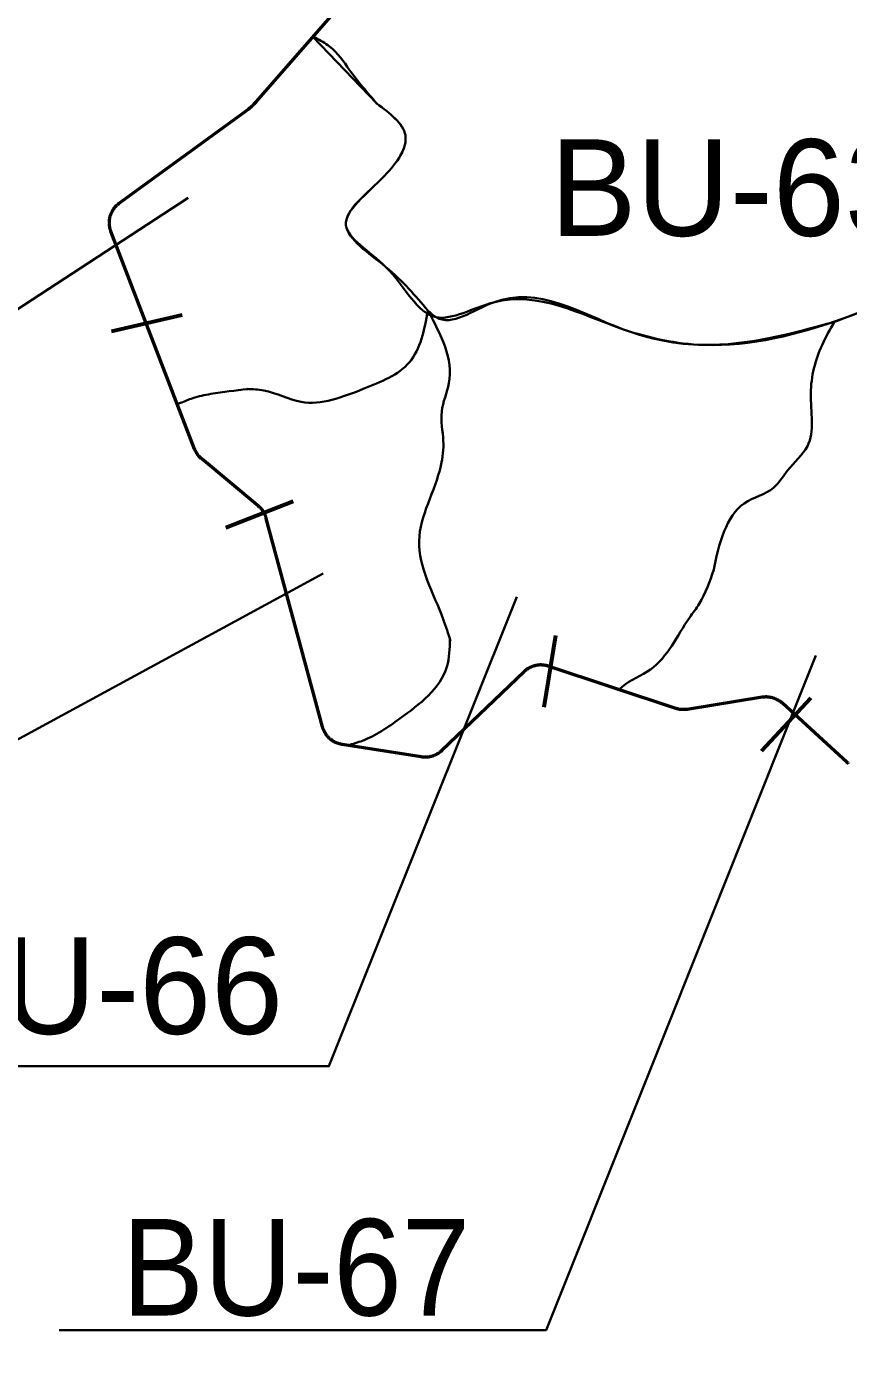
# Model space of a CAD drawing. Extents: x 553962 to 842807, y 8883888 to 9032388.
# Drawn here: x 651378 to 654778, y 8952723 to 8958207 of the extents above; entities that cross this region are included whole.
import ezdxf

# ---------------------------------------------------------------- set-up
doc = ezdxf.new("R2010")
doc.units = 0
doc.header["$LTSCALE"] = 150
for name, color, linetype, lineweight in [('20', 7, 'Continuous', 35), ('40', 7, 'Continuous', 60), ('60', 7, 'Continuous', 53), ('9', 7, 'Continuous', 90)]:
    doc.layers.add(name, color=color, linetype=linetype, lineweight=lineweight)

msp = doc.modelspace()

# ---------------------------------------------------------------- linework, layer by layer
at = {"layer": '20'}
for p, q in [((652563.7, 8958165), (653032.2, 8958701.7)), ((652563.2, 8958164.5), (652826.9, 8957888.7)), ((654720.4, 8956985.1), (654717.3, 8956984)), ((652293, 8956706.9), (652289, 8956707.3)), ((653830.5, 8955462.4), (653829, 8955462.9))]:
    msp.add_line(p, q, dxfattribs=at)
for points in [[(652002.6, 8956643.4), (651727.4, 8957359.4), (651726.4, 8957362), (651725.5, 8957364.7), (651724.7, 8957367.4), (651723.9, 8957370.2), (651723.2, 8957372.9), (651722.7, 8957375.7), (651722.1, 8957378.4), (651721.7, 8957381.2), (651721.3, 8957384), (651721.1, 8957386.9), (651720.9, 8957389.7), (651720.8, 8957392.5), (651720.7, 8957395.3), (651720.8, 8957398.2), (651720.9, 8957401), (651721.1, 8957403.8), (651721.4, 8957406.6), (651721.7, 8957409.4), (651722.2, 8957412.2), (651722.7, 8957415), (651723.3, 8957417.8), (651724, 8957420.5), (651724.7, 8957423.2), (651725.5, 8957425.9), (651726.4, 8957428.6), (651727.4, 8957431.3), (651728.5, 8957433.9), (651729.6, 8957436.5), (651730.8, 8957439.1), (651732.1, 8957441.6), (651733.4, 8957444.1), (651734.8, 8957446.5), (651736.3, 8957448.9), (651737.9, 8957451.3), (651739.5, 8957453.6), (651741.2, 8957455.9), (651742.9, 8957458.1), (651744.7, 8957460.3), (651746.6, 8957462.4), (651748.5, 8957464.5), (651750.5, 8957466.5), (651752.6, 8957468.4), (651754.7, 8957470.3), (651756.8, 8957472.2), (651759, 8957474), (651761.3, 8957475.7), (651761.8, 8957476), (652295.9, 8957865.8), (652299.1, 8957868.2), (652302.3, 8957870.6), (652305.4, 8957873.1), (652308.4, 8957875.7), (652311.5, 8957878.3), (652314.4, 8957881.1), (652317.3, 8957883.8), (652320.1, 8957886.6), (652322.9, 8957889.5), (652325.7, 8957892.4), (652328.3, 8957895.4), (652328.7, 8957895.8), (652563.2, 8958164.5)], [(652089.1, 8956431.6), (652087.4, 8956433.8), (652085.7, 8956436.1), (652084.1, 8956438.5), (652082.6, 8956440.8), (652081.1, 8956443.2), (652079.7, 8956445.7), (652078.3, 8956448.2), (652077, 8956450.7), (652075.8, 8956453.2), (652074.7, 8956455.8), (652073.7, 8956458.5), (652073.6, 8956458.6), (652003.1, 8956642.1)], [(652710.8, 8955231.7), (652683.3, 8955236.1), (652680.5, 8955236.5), (652677.7, 8955237.1), (652675, 8955237.7), (652672.2, 8955238.5), (652669.5, 8955239.2), (652666.8, 8955240.1), (652664.1, 8955241.1), (652661.5, 8955242.1), (652658.9, 8955243.2), (652656.3, 8955244.4), (652653.8, 8955245.6), (652651.3, 8955246.9), (652648.8, 8955248.3), (652646.4, 8955249.8), (652644, 8955251.3), (652641.7, 8955252.9), (652639.4, 8955254.5), (652637.1, 8955256.2), (652634.9, 8955258), (652632.8, 8955259.8), (652630.7, 8955261.8), (652628.6, 8955263.7), (652626.7, 8955265.7), (652624.7, 8955267.8), (652622.9, 8955269.9), (652621.1, 8955272.1), (652619.3, 8955274.3), (652617.6, 8955276.6), (652616, 8955278.9), (652614.5, 8955281.3), (652613, 8955283.7), (652611.6, 8955286.2), (652610.2, 8955288.7), (652609, 8955291.2), (652607.8, 8955293.7), (652606.7, 8955296.3), (652605.6, 8955299), (652604.6, 8955301.6), (652603.7, 8955304.3), (652602.9, 8955307), (652602.4, 8955308.8), (652370.1, 8956171.6), (652369.3, 8956174.3), (652368.5, 8956177.1), (652367.6, 8956179.7), (652366.6, 8956182.4), (652365.5, 8956185), (652364.3, 8956187.6), (652363.1, 8956190.1), (652361.8, 8956192.6), (652360.5, 8956195.1), (652359, 8956197.6), (652357.5, 8956199.9), (652356, 8956202.3), (652354.3, 8956204.6), (652352.6, 8956206.9), (652350.9, 8956209.1), (652349, 8956211.2), (652347.2, 8956213.3), (652345.2, 8956215.4), (652343.2, 8956217.4), (652341.1, 8956219.3), (652339, 8956221.2), (652337.5, 8956222.5), (652103, 8956417.5), (652100.9, 8956419.4), (652098.8, 8956421.3), (652096.7, 8956423.2), (652094.7, 8956425.3), (652092.8, 8956427.3), (652091, 8956429.5), (652089.1, 8956431.6)], [(653082.6, 8955200), (653084.9, 8955201.6), (653087.2, 8955203.2), (653089.4, 8955205), (653091.6, 8955206.8), (653093.7, 8955208.7), (653095.8, 8955210.6), (653436.2, 8955537), (653436.9, 8955537.7), (653439, 8955539.6), (653441.1, 8955541.4), (653443.3, 8955543.2), (653445.5, 8955545), (653447.8, 8955546.6), (653450.2, 8955548.2), (653452.5, 8955549.7), (653455, 8955551.2), (653457.4, 8955552.6), (653459.9, 8955553.9), (653462.5, 8955555.2), (653465, 8955556.3), (653467.6, 8955557.4), (653470.3, 8955558.5), (653472.9, 8955559.4), (653475.6, 8955560.3), (653478.3, 8955561.1), (653481.1, 8955561.8), (653483.8, 8955562.5), (653486.6, 8955563.1), (653489.4, 8955563.5), (653492.2, 8955564), (653495, 8955564.3), (653497.8, 8955564.6), (653500.6, 8955564.7), (653503.5, 8955564.8), (653506.3, 8955564.8), (653509.1, 8955564.8), (653511.9, 8955564.6), (653514.8, 8955564.4), (653517.6, 8955564.1), (653520.4, 8955563.7), (653523.2, 8955563.2), (653525.9, 8955562.7), (653528.7, 8955562.1), (653531.4, 8955561.4), (653534.2, 8955560.6), (653536.8, 8955559.8), (653829.5, 8955462.7)], [(654774.8, 8955159.6), (654772.6, 8955161.5), (654771.6, 8955162.4), (654505.1, 8955406.1), (654503, 8955408), (654500.8, 8955409.8), (654498.6, 8955411.6), (654496.4, 8955413.3), (654494.1, 8955414.9), (654491.7, 8955416.5), (654489.3, 8955418), (654486.9, 8955419.4), (654484.4, 8955420.7), (654481.8, 8955422), (654479.3, 8955423.2), (654476.7, 8955424.4), (654474.1, 8955425.4), (654471.5, 8955426.4), (654468.8, 8955427.3), (654466.1, 8955428.2), (654463.3, 8955429), (654460.6, 8955429.7), (654457.8, 8955430.3), (654455.1, 8955430.8), (654452.3, 8955431.2), (654449.5, 8955431.6), (654446.7, 8955431.9), (654443.8, 8955432.1), (654441, 8955432.3), (654438.2, 8955432.3), (654435.4, 8955432.3), (654432.5, 8955432.2), (654429.7, 8955432), (654426.9, 8955431.7), (654424.1, 8955431.4), (654421.8, 8955431.1), (654111.4, 8955381.1), (654108.6, 8955380.7), (654105.8, 8955380.4), (654103, 8955380.2), (654100.1, 8955380), (654097.3, 8955379.9), (654094.5, 8955379.9), (654091.7, 8955379.9), (654088.8, 8955380.1), (654086, 8955380.3), (654083.2, 8955380.6), (654080.4, 8955381), (654077.6, 8955381.5), (654074.8, 8955382), (654072.1, 8955382.7), (654069.3, 8955383.3), (654066.6, 8955384.1), (654064, 8955385), (653830.5, 8955462.4)], [(652712.1, 8955231.5), (653010.9, 8955184), (653012.6, 8955183.8), (653015.4, 8955183.4), (653018.2, 8955183.1), (653021, 8955182.9), (653023.8, 8955182.8), (653026.7, 8955182.8), (653029.5, 8955182.8), (653032.3, 8955183), (653035.1, 8955183.2), (653037.9, 8955183.4), (653040.7, 8955183.8), (653043.5, 8955184.2), (653046.3, 8955184.8), (653049.1, 8955185.3), (653051.8, 8955186), (653054.6, 8955186.8), (653057.3, 8955187.6), (653059.9, 8955188.5), (653062.6, 8955189.5), (653065.2, 8955190.6), (653067.8, 8955191.7), (653070.4, 8955192.9), (653072.9, 8955194.2), (653075.4, 8955195.5), (653077.8, 8955196.9), (653080.2, 8955198.4), (653082.6, 8955200)]]:
    msp.add_lwpolyline(points, dxfattribs=at)
for points in [[(657836.1, 8962063), (657516.9, 8961702.6), (657287.8, 8961510.1), (657005.4, 8961440.5), (656903.1, 8961280.8), (656489.7, 8960883.6), (656367, 8960554), (656244.2, 8960275.5), (656461.1, 8960083), (656125.5, 8959583.5), (656002.7, 8959268.1), (655892.2, 8958970.8), (655875.9, 8958766.1), (655834.9, 8958479.4), (655843.5, 8958403.3), (655810.8, 8958169.9), (655724.8, 8957948.7), (655561.2, 8957592.5), (655350, 8957384.8), (655198.6, 8957233.3), (654760.7, 8956999.9), (654179.6, 8956889.4), (653844, 8956954.9), (653309.5, 8957065.4), (653072.2, 8957004), (652863.4, 8957212.9), (652699.7, 8957384.8), (652859.3, 8957589.6), (652945.3, 8957757.5), (652826.9, 8957888.7)], [(652827.9, 8957887.6), (652714.5, 8958027.3), (652632.2, 8958124.7), (652573, 8958160.8), (652564.3, 8958165.8)], [(652827.9, 8957887.6), (652714.5, 8958027.3), (652632.2, 8958124.7), (652573, 8958160.8), (652564.3, 8958165.8)], [(653037.9, 8957032.2), (652863.4, 8957212.9), (652699.7, 8957384.8), (652859.3, 8957589.6), (652945.3, 8957757.5), (652826.9, 8957888.7)], [(652826.9, 8957888.7), (652945.3, 8957757.5), (652859.3, 8957589.6), (652699.7, 8957384.8), (652863.4, 8957212.9), (653037.9, 8957032.2)], [(655331.3, 8957366.2), (655198.6, 8957233.3), (654760.7, 8956999.9), (654718.7, 8956984.5)], [(654718.7, 8956984.5), (654760.7, 8956999.9), (655198.6, 8957233.3), (655331.3, 8957366.2)], [(654717.3, 8956984), (654179.6, 8956889.4), (653844, 8956954.9), (653309.5, 8957065.4), (653072.2, 8957004), (653039.2, 8957031.1)], [(654717.3, 8956984), (654179.6, 8956889.4), (653844, 8956954.9), (653309.5, 8957065.4), (653072.2, 8957004), (653039.2, 8957031.1)], [(653039.1, 8957031.2), (652961.9, 8956817.7), (652771.4, 8956707.3), (652514, 8956653.8), (652360.2, 8956700.6), (652289, 8956707.3)], [(652289, 8956707.3), (652360.2, 8956700.6), (652514, 8956653.8), (652771.4, 8956707.3), (652961.9, 8956817.7), (653039.1, 8957031.2)], [(652289, 8956707.3), (652360.2, 8956700.6), (652514, 8956653.8), (652771.4, 8956707.3), (652961.9, 8956817.7), (653039.1, 8957031.2)], [(653038.9, 8957031.4), (653125.7, 8956730.7), (653095.6, 8956613.6), (653102.3, 8956493.2), (653092.3, 8956389.5), (653002, 8956078.4), (653102.3, 8955753.9), (653132.4, 8955663.6)], [(653038.9, 8957031.4), (653125.7, 8956730.7), (653095.6, 8956613.6), (653102.3, 8956493.2), (653092.3, 8956389.5), (653002, 8956078.4), (653102.3, 8955753.9), (653132.4, 8955663.6)], [(653038.9, 8957031.4), (653125.7, 8956730.7), (653095.6, 8956613.6), (653102.3, 8956493.2), (653092.3, 8956389.5), (653002, 8956078.4), (653102.3, 8955753.9), (653132.4, 8955663.6)], [(654219.7, 8955952.5), (654264.8, 8956119.1), (654347.1, 8956233.7), (654468.8, 8956298.1), (654526, 8956369.7), (654608.3, 8956470), (654622.6, 8956688.4), (654669.2, 8956888.9), (654720.4, 8956985.1)], [(654219.7, 8955952.5), (654264.8, 8956119.1), (654347.1, 8956233.7), (654468.8, 8956298.1), (654526, 8956369.7), (654608.3, 8956470), (654622.6, 8956688.4), (654669.2, 8956888.9), (654720.4, 8956985.1)], [(654720.4, 8956985.1), (654669.2, 8956888.9), (654622.6, 8956688.4), (654608.3, 8956470), (654526, 8956369.7), (654468.8, 8956298.1), (654347.1, 8956233.7), (654264.8, 8956119.1), (654219.7, 8955952.5)], [(652293, 8956706.9), (652140.8, 8956686.4), (652065.6, 8956669.2), (652014.8, 8956649.2), (652002.2, 8956644.5)], [(652002.2, 8956644.5), (652014.8, 8956649.2), (652065.6, 8956669.2), (652140.8, 8956686.4), (652293, 8956706.9)], [(652293, 8956706.9), (652140.8, 8956686.4), (652065.6, 8956669.2), (652014.8, 8956649.2), (652002.2, 8956644.5)], [(653829, 8955462.9), (653842.3, 8955474.7), (653958.9, 8955546.1), (654120.8, 8955760.3), (654160.8, 8955817.8), (654221.6, 8955959.4)], [(653829, 8955462.9), (653842.3, 8955474.7), (653958.9, 8955546.1), (654120.8, 8955760.3), (654160.8, 8955817.8), (654221.6, 8955959.4)], [(654221.6, 8955959.4), (654160.8, 8955817.8), (654120.8, 8955760.3), (653958.9, 8955546.1), (653842.3, 8955474.7), (653829, 8955462.9)], [(653129.6, 8955672.1), (653117.4, 8955557.7), (652922.6, 8955342.6), (652767.9, 8955251.3), (652707.6, 8955232.2)], [(653129.6, 8955672.1), (653117.4, 8955557.7), (652922.6, 8955342.6), (652767.9, 8955251.3), (652707.6, 8955232.2)], [(653129.6, 8955672.1), (653117.4, 8955557.7), (652922.6, 8955342.6), (652767.9, 8955251.3), (652707.6, 8955232.2)]]:
    msp.add_spline(points, degree=3, dxfattribs=at)
at = {"layer": '40'}
for p, q in [((651730.2, 8956946.1), (652022.6, 8957013.3)), ((652202.2, 8956133.9), (652481.5, 8956243.4)), ((653519.1, 8955390.6), (653567.9, 8955686.7)), ((654419, 8955209), (654623.3, 8955428.7))]:
    msp.add_line(p, q, dxfattribs=at)
at = {"layer": '40', "lineweight": 35}
for points in [[(652046.7, 8957498.3), (650857.4, 8956721.2), (649037.1, 8956721.2)], [(652604.9, 8955944), (651221.5, 8955191.1), (649182.7, 8955191.1)], [(653405.9, 8955846.9), (652629.2, 8953903.9), (650711.8, 8953903.9)], [(654643.7, 8955604), (653527.2, 8952811), (651512.7, 8952811)]]:
    msp.add_lwpolyline(points, dxfattribs=at)
at = {"layer": '60'}
for points in [[(652089.1, 8956431.6), (652087.4, 8956433.8), (652085.7, 8956436.1), (652084.1, 8956438.5), (652082.6, 8956440.8), (652081.1, 8956443.2), (652079.7, 8956445.7), (652078.3, 8956448.2), (652077, 8956450.7), (652075.8, 8956453.2), (652074.7, 8956455.8), (652073.7, 8956458.5), (652073.6, 8956458.6), (651727.4, 8957359.4), (651726.4, 8957362), (651725.5, 8957364.7), (651724.7, 8957367.4), (651723.9, 8957370.2), (651723.2, 8957372.9), (651722.7, 8957375.7), (651722.1, 8957378.4), (651721.7, 8957381.2), (651721.3, 8957384), (651721.1, 8957386.9), (651720.9, 8957389.7), (651720.8, 8957392.5), (651720.7, 8957395.3), (651720.8, 8957398.2), (651720.9, 8957401), (651721.1, 8957403.8), (651721.4, 8957406.6), (651721.7, 8957409.4), (651722.2, 8957412.2), (651722.7, 8957415), (651723.3, 8957417.8), (651724, 8957420.5), (651724.7, 8957423.2), (651725.5, 8957425.9), (651726.4, 8957428.6), (651727.4, 8957431.3), (651728.5, 8957433.9), (651729.6, 8957436.5), (651730.8, 8957439.1), (651732.1, 8957441.6), (651733.4, 8957444.1), (651734.8, 8957446.5), (651736.3, 8957448.9), (651737.9, 8957451.3), (651739.5, 8957453.6), (651741.2, 8957455.9), (651742.9, 8957458.1), (651744.7, 8957460.3), (651746.6, 8957462.4), (651748.5, 8957464.5), (651750.5, 8957466.5), (651752.6, 8957468.4), (651754.7, 8957470.3), (651756.8, 8957472.2), (651759, 8957474), (651761.3, 8957475.7), (651761.8, 8957476), (652295.9, 8957865.8), (652299.1, 8957868.2), (652302.3, 8957870.6), (652305.4, 8957873.1), (652308.4, 8957875.7), (652311.5, 8957878.3), (652314.4, 8957881.1), (652317.3, 8957883.8), (652320.1, 8957886.6), (652322.9, 8957889.5), (652325.7, 8957892.4), (652328.3, 8957895.4), (652328.7, 8957895.8), (653033.4, 8958703.2)], [(653082.6, 8955200), (653080.2, 8955198.4), (653077.8, 8955196.9), (653075.4, 8955195.5), (653072.9, 8955194.2), (653070.4, 8955192.9), (653067.8, 8955191.7), (653065.2, 8955190.6), (653062.6, 8955189.5), (653059.9, 8955188.5), (653057.3, 8955187.6), (653054.6, 8955186.8), (653051.8, 8955186), (653049.1, 8955185.3), (653046.3, 8955184.8), (653043.5, 8955184.2), (653040.7, 8955183.8), (653037.9, 8955183.4), (653035.1, 8955183.2), (653032.3, 8955183), (653029.5, 8955182.8), (653026.7, 8955182.8), (653023.8, 8955182.8), (653021, 8955182.9), (653018.2, 8955183.1), (653015.4, 8955183.4), (653012.6, 8955183.8), (653010.9, 8955184), (652683.3, 8955236.1), (652680.5, 8955236.5), (652677.7, 8955237.1), (652675, 8955237.7), (652672.2, 8955238.5), (652669.5, 8955239.2), (652666.8, 8955240.1), (652664.1, 8955241.1), (652661.5, 8955242.1), (652658.9, 8955243.2), (652656.3, 8955244.4), (652653.8, 8955245.6), (652651.3, 8955246.9), (652648.8, 8955248.3), (652646.4, 8955249.8), (652644, 8955251.3), (652641.7, 8955252.9), (652639.4, 8955254.5), (652637.1, 8955256.2), (652634.9, 8955258), (652632.8, 8955259.8), (652630.7, 8955261.8), (652628.6, 8955263.7), (652626.7, 8955265.7), (652624.7, 8955267.8), (652622.9, 8955269.9), (652621.1, 8955272.1), (652619.3, 8955274.3), (652617.6, 8955276.6), (652616, 8955278.9), (652614.5, 8955281.3), (652613, 8955283.7), (652611.6, 8955286.2), (652610.2, 8955288.7), (652609, 8955291.2), (652607.8, 8955293.7), (652606.7, 8955296.3), (652605.6, 8955299), (652604.6, 8955301.6), (652603.7, 8955304.3), (652602.9, 8955307), (652602.4, 8955308.8), (652370.1, 8956171.6), (652369.3, 8956174.3), (652368.5, 8956177.1), (652367.6, 8956179.7), (652366.6, 8956182.4), (652365.5, 8956185), (652364.3, 8956187.6), (652363.1, 8956190.1), (652361.8, 8956192.6), (652360.5, 8956195.1), (652359, 8956197.6), (652357.5, 8956199.9), (652356, 8956202.3), (652354.3, 8956204.6), (652352.6, 8956206.9), (652350.9, 8956209.1), (652349, 8956211.2), (652347.2, 8956213.3), (652345.2, 8956215.4), (652343.2, 8956217.4), (652341.1, 8956219.3), (652339, 8956221.2), (652337.5, 8956222.5), (652103, 8956417.5), (652100.9, 8956419.4), (652098.8, 8956421.3), (652096.7, 8956423.2), (652094.7, 8956425.3), (652092.8, 8956427.3), (652091, 8956429.5), (652089.1, 8956431.6)], [(654774.8, 8955159.6), (654772.6, 8955161.5), (654771.6, 8955162.4), (654505.1, 8955406.1), (654503, 8955408), (654500.8, 8955409.8), (654498.6, 8955411.6), (654496.4, 8955413.3), (654494.1, 8955414.9), (654491.7, 8955416.5), (654489.3, 8955418), (654486.9, 8955419.4), (654484.4, 8955420.7), (654481.8, 8955422), (654479.3, 8955423.2), (654476.7, 8955424.4), (654474.1, 8955425.4), (654471.5, 8955426.4), (654468.8, 8955427.3), (654466.1, 8955428.2), (654463.3, 8955429), (654460.6, 8955429.7), (654457.8, 8955430.3), (654455.1, 8955430.8), (654452.3, 8955431.2), (654449.5, 8955431.6), (654446.7, 8955431.9), (654443.8, 8955432.1), (654441, 8955432.3), (654438.2, 8955432.3), (654435.4, 8955432.3), (654432.5, 8955432.2), (654429.7, 8955432), (654426.9, 8955431.7), (654424.1, 8955431.4), (654421.8, 8955431.1), (654111.4, 8955381.1), (654108.6, 8955380.7), (654105.8, 8955380.4), (654103, 8955380.2), (654100.1, 8955380), (654097.3, 8955379.9), (654094.5, 8955379.9), (654091.7, 8955379.9), (654088.8, 8955380.1), (654086, 8955380.3), (654083.2, 8955380.6), (654080.4, 8955381), (654077.6, 8955381.5), (654074.8, 8955382), (654072.1, 8955382.7), (654069.3, 8955383.3), (654066.6, 8955384.1), (654064, 8955385), (653536.8, 8955559.8), (653534.2, 8955560.6), (653531.4, 8955561.4), (653528.7, 8955562.1), (653525.9, 8955562.7), (653523.2, 8955563.2), (653520.4, 8955563.7), (653517.6, 8955564.1), (653514.8, 8955564.4), (653511.9, 8955564.6), (653509.1, 8955564.8), (653506.3, 8955564.8), (653503.5, 8955564.8), (653500.6, 8955564.7), (653497.8, 8955564.6), (653495, 8955564.3), (653492.2, 8955564), (653489.4, 8955563.5), (653486.6, 8955563.1), (653483.8, 8955562.5), (653481.1, 8955561.8), (653478.3, 8955561.1), (653475.6, 8955560.3), (653472.9, 8955559.4), (653470.3, 8955558.5), (653467.6, 8955557.4), (653465, 8955556.3), (653462.5, 8955555.2), (653459.9, 8955553.9), (653457.4, 8955552.6), (653455, 8955551.2), (653452.5, 8955549.7), (653450.2, 8955548.2), (653447.8, 8955546.6), (653445.5, 8955545), (653443.3, 8955543.2), (653441.1, 8955541.4), (653439, 8955539.6), (653436.9, 8955537.7), (653436.2, 8955537), (653095.8, 8955210.6), (653093.7, 8955208.7), (653091.6, 8955206.8), (653089.4, 8955205), (653087.2, 8955203.2), (653084.9, 8955201.6), (653082.6, 8955200)], [(654779.2, 8955156.1), (654777, 8955157.8), (654774.8, 8955159.6)]]:
    msp.add_lwpolyline(points, dxfattribs=at)
at = {"layer": '9'}
msp.add_spline([(637260.6, 8972975.8), (641524.5, 8971056.2), (652526.1, 8965412.7), (653164.3, 8965062.8), (670790.5, 8953770.1), (686194, 8943929.9), (696283.3, 8937647.1)], degree=3, dxfattribs=at)

# ---------------------------------------------------------------- texts
at = {"layer": '40'}
for s, p in [('BU-63', (653544.6, 8957340.8)), ('BU-66', (650923.3, 8954037.8))]:
    msp.add_text(s, height=400, dxfattribs=at).set_placement(p)
at = {"layer": '40', "width": 0.95}
msp.add_text('BU-67', height=400, dxfattribs=at).set_placement((651772.8, 8952872.1))

doc.saveas('drawing.dxf')
